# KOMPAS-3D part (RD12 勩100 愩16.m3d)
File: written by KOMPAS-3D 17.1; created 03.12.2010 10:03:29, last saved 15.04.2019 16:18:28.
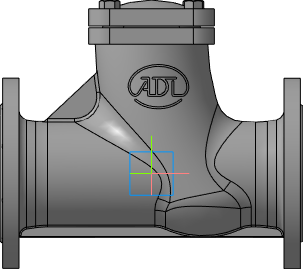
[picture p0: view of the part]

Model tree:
1. Плоскость XY
2. Плоскость ZX
3. Плоскость ZY
4. Ось X
5. Ось Y
6. Ось Z
7. Начало координат
8. Операция без истории:4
